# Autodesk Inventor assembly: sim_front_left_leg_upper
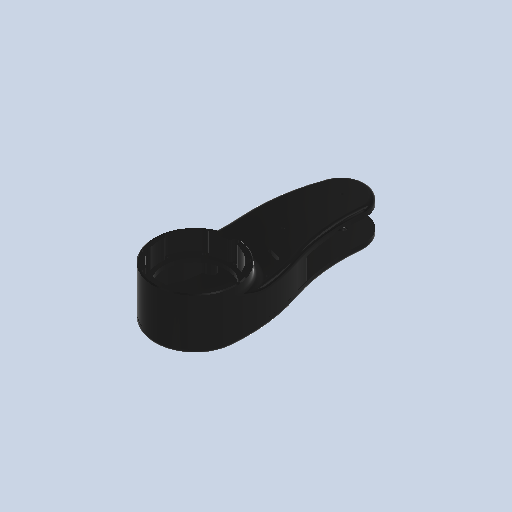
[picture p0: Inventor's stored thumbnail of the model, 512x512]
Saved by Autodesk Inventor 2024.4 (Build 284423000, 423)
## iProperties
Created: 2026-01
Part Number: sim_front_left_leg_upper
Document SubType Name: Assembly
Designer: AdminForWorker
Title: front_right_leg_upper v3
Author: AdminForWorker
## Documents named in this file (3)
- c:\worker\convert-fusion-r06-cosv3\tmp\job-1\15\temp\files\c4e88d80-fe8b-4503-85d0-43d6363d01f0\379c6d3c-6f7c-408b-9736-916467327438.iam
- c:\worker\convert-fusion-r06-cosv3\tmp\job-1\15\temp\files\c4e88d80-fe8b-4503-85d0-43d6363d01f0\leg_upper_inner.ipt
- c:\worker\convert-fusion-r06-cosv3\tmp\job-1\15\temp\files\c4e88d80-fe8b-4503-85d0-43d6363d01f0\leg_upper_outer.ipt
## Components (2 placed, 2 different names)
1. leg_upper_inner:1
2. leg_upper_outer:1
